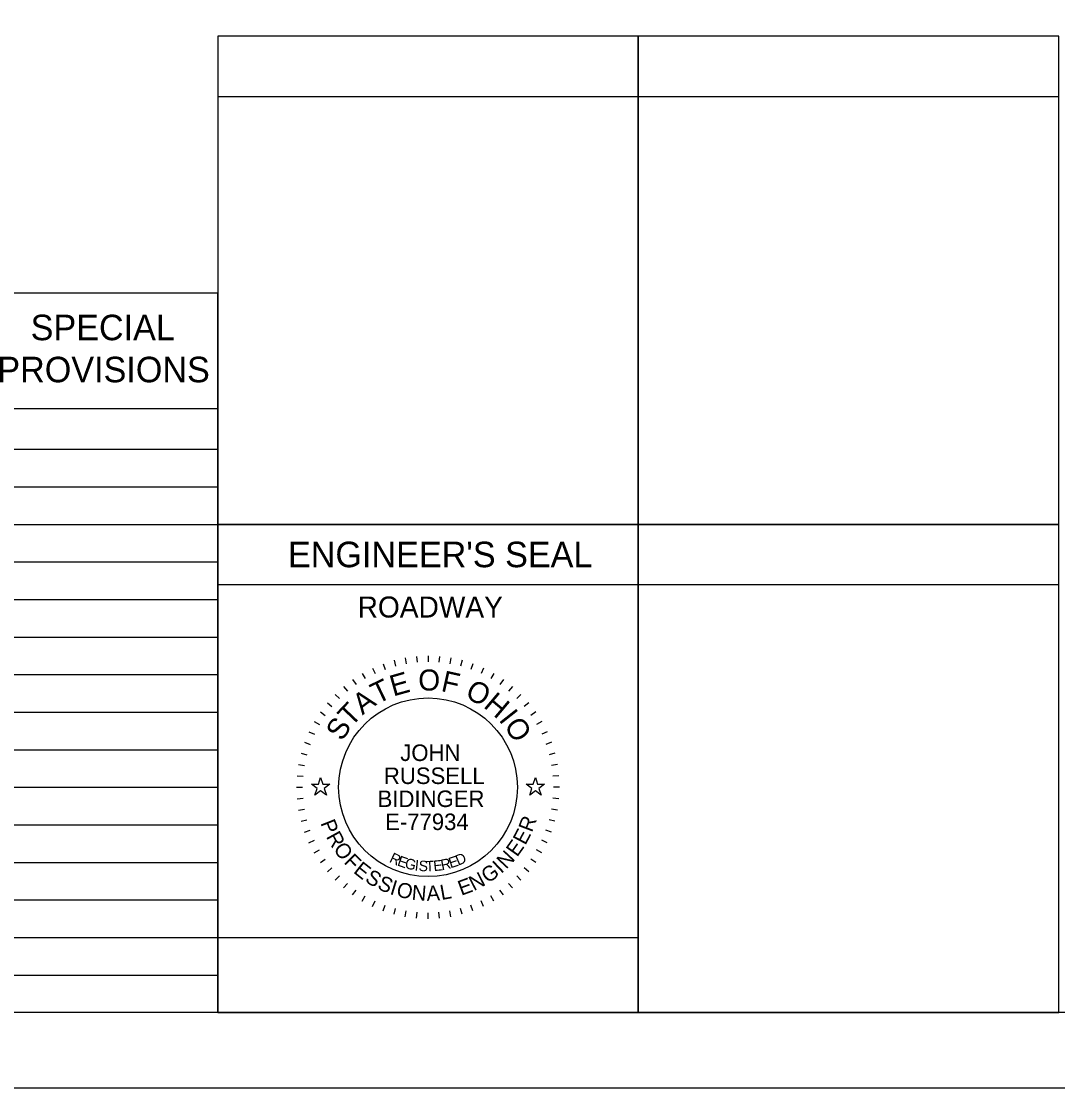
# Model space of a CAD drawing. Extents: x 0 to 34, y 0 to 22.
# Drawn here: x 22.29 to 29.19, y 0 to 7.1 of the extents above; entities that cross this region are included whole.
import ezdxf

# ---------------------------------------------------------------- set-up
doc = ezdxf.new("R2010")
doc.units = 0
for name, color, linetype in [('SH_Border', 7, 'Continuous'), ('SH_Cut_Line', 7, 'Continuous'), ('SH_Data', 7, 'Continuous'), ('SH_Seal', 7, 'Continuous'), ('SH_Text', 7, 'Continuous')]:
    doc.layers.add(name, color=color, linetype=linetype)

msp = doc.modelspace()

# ---------------------------------------------------------------- linework, layer by layer
at = {"layer": 'SH_Border'}
msp.add_lwpolyline([(1.5, 21.5), (33.5, 21.5), (33.5, 0.5), (1.5, 0.5)], close=True, dxfattribs=at)
at = {"layer": 'SH_Cut_Line'}
msp.add_lwpolyline([(0, 0), (34, 0), (34, 22), (0, 22)], close=True, dxfattribs=at)
at = {"layer": 'SH_Data'}
for p, q in [((23.6, 6.6), (26.4, 6.6)), ((26.4, 6.6), (29.2, 6.6)), ((10.15, 5.2917), (23.6, 5.2917)), ((23.6, 0.5), (23.6, 5.2917)), ((10.15, 4.5209), (23.6, 4.5209)), ((10.15, 4.25), (23.6, 4.25)), ((10.15, 4), (23.6, 4)), ((10.15, 3.75), (23.6, 3.75)), ((23.6, 0.5), (23.6, 3.75)), ((23.6, 3.75), (26.4, 3.75)), ((26.4, 3.75), (26.4, 0.5)), ((26.4, 0.5), (26.4, 3.75)), ((10.15, 3.5), (23.6, 3.5)), ((23.6, 3.35), (26.4, 3.35)), ((23.6, 3.35), (26.4, 3.35)), ((26.4, 3.35), (29.2, 3.35)), ((10.15, 3.25), (23.6, 3.25)), ((10.15, 3), (23.6, 3)), ((10.15, 2.75), (23.6, 2.75)), ((10.15, 2.5), (23.6, 2.5)), ((10.15, 2.25), (23.6, 2.25)), ((10.15, 2), (23.6, 2)), ((10.15, 1.75), (23.6, 1.75)), ((10.15, 1.5), (23.6, 1.5)), ((10.15, 1.25), (23.6, 1.25)), ((10.15, 1), (23.6, 1)), ((10.15, 0.75), (23.6, 0.75)), ((23.6, 0.5), (26.4, 0.5))]:
    msp.add_line(p, q, dxfattribs=at)
for points in [[(26.4, 7), (23.6, 7), (23.6, 3.75), (26.4, 3.75)], [(29.2, 7), (26.4, 7), (26.4, 3.75), (29.2, 3.75)], [(26.4, 3.75), (23.6, 3.75), (23.6, 0.5), (26.4, 0.5)], [(29.2, 3.75), (26.4, 3.75), (26.4, 0.5), (29.2, 0.5)], [(23.6, 0.5), (23.6, 1), (26.4, 1), (26.4, 0.5)]]:
    msp.add_lwpolyline(points, close=True, dxfattribs=at)
at = {"layer": 'SH_Seal'}
for p, q in [((24.7735, 2.8452), (24.7839, 2.8065)), ((24.8481, 2.8617), (24.855, 2.8223)), ((24.9237, 2.8717), (24.9272, 2.8318)), ((25, 2.875), (25, 2.835)), ((25.0763, 2.8717), (25.0728, 2.8318)), ((25.1519, 2.8617), (25.145, 2.8223)), ((25.2265, 2.8452), (25.2161, 2.8065)), ((24.6302, 2.793), (24.6471, 2.7568)), ((24.7007, 2.8222), (24.7144, 2.7846)), ((25.2993, 2.8222), (25.2856, 2.7846)), ((25.3698, 2.793), (25.3529, 2.7568)), ((24.4981, 2.7168), (24.5211, 2.684)), ((24.5625, 2.7578), (24.5825, 2.7231)), ((25.4375, 2.7578), (25.4175, 2.7231)), ((25.5019, 2.7168), (25.4789, 2.684)), ((24.4376, 2.6703), (24.4633, 2.6396)), ((25.5624, 2.6703), (25.5367, 2.6396)), ((24.3297, 2.5624), (24.3604, 2.5367)), ((24.3813, 2.6187), (24.4096, 2.5904)), ((25.6187, 2.6187), (25.5904, 2.5904)), ((25.6703, 2.5624), (25.6396, 2.5367)), ((24.2832, 2.5019), (24.316, 2.4789)), ((25.7168, 2.5019), (25.684, 2.4789)), ((24.2422, 2.4375), (24.2769, 2.4175)), ((25.7578, 2.4375), (25.7231, 2.4175)), ((24.207, 2.3698), (24.2432, 2.3529)), ((25.793, 2.3698), (25.7568, 2.3529)), ((24.1778, 2.2993), (24.2154, 2.2856)), ((25.8222, 2.2993), (25.7846, 2.2856)), ((24.1548, 2.2265), (24.1935, 2.2161)), ((25.8452, 2.2265), (25.8065, 2.2161)), ((24.1383, 2.1519), (24.1777, 2.145)), ((25.8617, 2.1519), (25.8223, 2.145)), ((24.1283, 2.0763), (24.1682, 2.0728)), ((25.8717, 2.0763), (25.8318, 2.0728)), ((24.125, 2), (24.165, 2)), ((25.875, 2), (25.835, 2)), ((24.1283, 1.9237), (24.1682, 1.9272)), ((25.8717, 1.9237), (25.8318, 1.9272)), ((24.1383, 1.8481), (24.1777, 1.855)), ((25.8617, 1.8481), (25.8223, 1.855)), ((24.1548, 1.7735), (24.1935, 1.7839)), ((25.8452, 1.7735), (25.8065, 1.7839)), ((24.1778, 1.7007), (24.2154, 1.7144)), ((25.8222, 1.7007), (25.7846, 1.7144)), ((24.207, 1.6302), (24.2432, 1.6471)), ((25.793, 1.6302), (25.7568, 1.6471)), ((24.2422, 1.5625), (24.2769, 1.5825)), ((25.7578, 1.5625), (25.7231, 1.5825)), ((24.2832, 1.4981), (24.316, 1.5211)), ((25.7168, 1.4981), (25.684, 1.5211)), ((24.3297, 1.4376), (24.3604, 1.4633)), ((25.6703, 1.4376), (25.6396, 1.4633)), ((24.3813, 1.3813), (24.4096, 1.4096)), ((24.4376, 1.3297), (24.4633, 1.3604)), ((25.5624, 1.3297), (25.5367, 1.3604)), ((25.6187, 1.3813), (25.5904, 1.4096)), ((24.4981, 1.2832), (24.5211, 1.316)), ((25.5019, 1.2832), (25.4789, 1.316)), ((24.5625, 1.2422), (24.5825, 1.2769)), ((24.6302, 1.207), (24.6471, 1.2432)), ((24.7007, 1.1778), (24.7144, 1.2154)), ((25.2993, 1.1778), (25.2856, 1.2154)), ((25.3698, 1.207), (25.3529, 1.2432)), ((25.4375, 1.2422), (25.4175, 1.2769)), ((24.7735, 1.1548), (24.7839, 1.1935)), ((24.8481, 1.1383), (24.855, 1.1777)), ((24.9237, 1.1283), (24.9272, 1.1682)), ((25, 1.125), (25, 1.165)), ((25.0763, 1.1283), (25.0728, 1.1682)), ((25.1519, 1.1383), (25.145, 1.1777)), ((25.2265, 1.1548), (25.2161, 1.1935))]:
    msp.add_line(p, q, dxfattribs=at)
for points in [[(24.2236, 2.02), (24.2705, 2.02), (24.285, 2.0645), (24.2995, 2.02), (24.3464, 2.02), (24.3085, 1.9924), (24.323, 1.9478), (24.285, 1.9754), (24.247, 1.9478), (24.2615, 1.9924)], [(25.6536, 2.02), (25.7005, 2.02), (25.715, 2.0645), (25.7295, 2.02), (25.7764, 2.02), (25.7385, 1.9924), (25.753, 1.9478), (25.715, 1.9754), (25.677, 1.9478), (25.6915, 1.9924)]]:
    msp.add_lwpolyline(points, close=True, dxfattribs=at)
msp.add_circle((25, 2), 0.595, dxfattribs=at)

# ---------------------------------------------------------------- texts
at = {"layer": 'SH_Data'}
for s, height, p in [("ENGINEER'S SEAL", 0.17, (24.0676, 3.465)), ('ROADWAY', 0.14, (24.5311, 3.13))]:
    msp.add_text(s, height=height, dxfattribs=at).set_placement(p)
at = {"layer": 'SH_Seal'}
for s, height, rotation, p in [('E', 0.14, 15.75706, (24.7684, 2.6038)), ('O', 0.14, 359.78119, (24.9347, 2.6443)), ('F', 0.14, 347.43619, (25.0811, 2.6417)), ('T', 0.14, 25.71674, (24.6616, 2.5518)), ('O', 0.14, 332.25863, (25.2398, 2.6015)), ('A', 0.14, 36.47472, (24.5634, 2.4781)), ('H', 0.14, 319.91363, (25.3632, 2.5361)), ('T', 0.14, 46.4344, (24.4883, 2.3964)), ('I', 0.14, 308.36695, (25.4665, 2.4483)), ('S', 0.14, 57.19238, (24.4281, 2.3014)), ('O', 0.14, 303.14906, (25.5021, 2.4089)), ('P', 0.1, 291.49398, (24.2823, 1.7621)), ('R', 0.1, 69.23216, (25.6919, 1.6954)), ('R', 0.1, 298.73106, (24.319, 1.6717)), ('E', 0.1, 61.99508, (25.6476, 1.6098)), ('E', 0.1, 54.75801, (25.5933, 1.5314)), ('O', 0.1, 306.46664, (24.3655, 1.5883)), ('R', 0.07, 334.48695, (24.7375, 1.5051)), ('N', 0.1, 47.02243, (25.5202, 1.4508)), ('F', 0.1, 314.7068, (24.4343, 1.4983)), ('E', 0.1, 321.43929, (24.4978, 1.4348)), ('E', 0.07, 341.03996, (24.7906, 1.4801)), ('G', 0.07, 347.47515, (24.8414, 1.4618)), ('I', 0.07, 353.78581, (24.9091, 1.4468)), ('S', 0.07, 356.89262, (24.9358, 1.4429)), ('T', 0.07, 3.00609, (24.9857, 1.4387)), ('E', 0.07, 6.01169, (25.0389, 1.4412)), ('R', 0.07, 11.91844, (25.0925, 1.4474)), ('E', 0.07, 17.68363, (25.1498, 1.4602)), ('D', 0.07, 23.30524, (25.201, 1.477)), ('I', 0.1, 43.28703, (25.4868, 1.4214)), ('S', 0.1, 328.67637, (24.5743, 1.3752)), ('N', 0.1, 27.31129, (25.3045, 1.3075)), ('G', 0.1, 35.04687, (25.3981, 1.357)), ('S', 0.1, 335.91345, (24.6564, 1.3266)), ('I', 0.1, 343.15053, (24.7406, 1.2897)), ('O', 0.1, 346.88592, (24.7839, 1.2751)), ('N', 0.1, 355.12608, (24.8888, 1.2517)), ('L', 0.1, 10.09874, (25.0894, 1.249)), ('E', 0.1, 20.07421, (25.2212, 1.277)), ('A', 0.1, 2.86166, (24.9923, 1.2437))]:
    msp.add_text(s, height=height, rotation=rotation, dxfattribs=at).set_placement(p)
for s, p in [('JOHN', (24.8153, 2.1749)), ('RUSSELL', (24.7062, 2.0216)), ('BIDINGER', (24.6644, 1.8684)), ('E-77934', (24.7145, 1.7151))]:
    msp.add_text(s, height=0.11, dxfattribs=at).set_placement(p)
at = {"layer": 'SH_Text'}
for s, p in [('SPECIAL', (22.3542, 4.9763)), ('PROVISIONS', (22.1323, 4.6963))]:
    msp.add_text(s, height=0.17, dxfattribs=at).set_placement(p)

doc.saveas('drawing.dxf')
